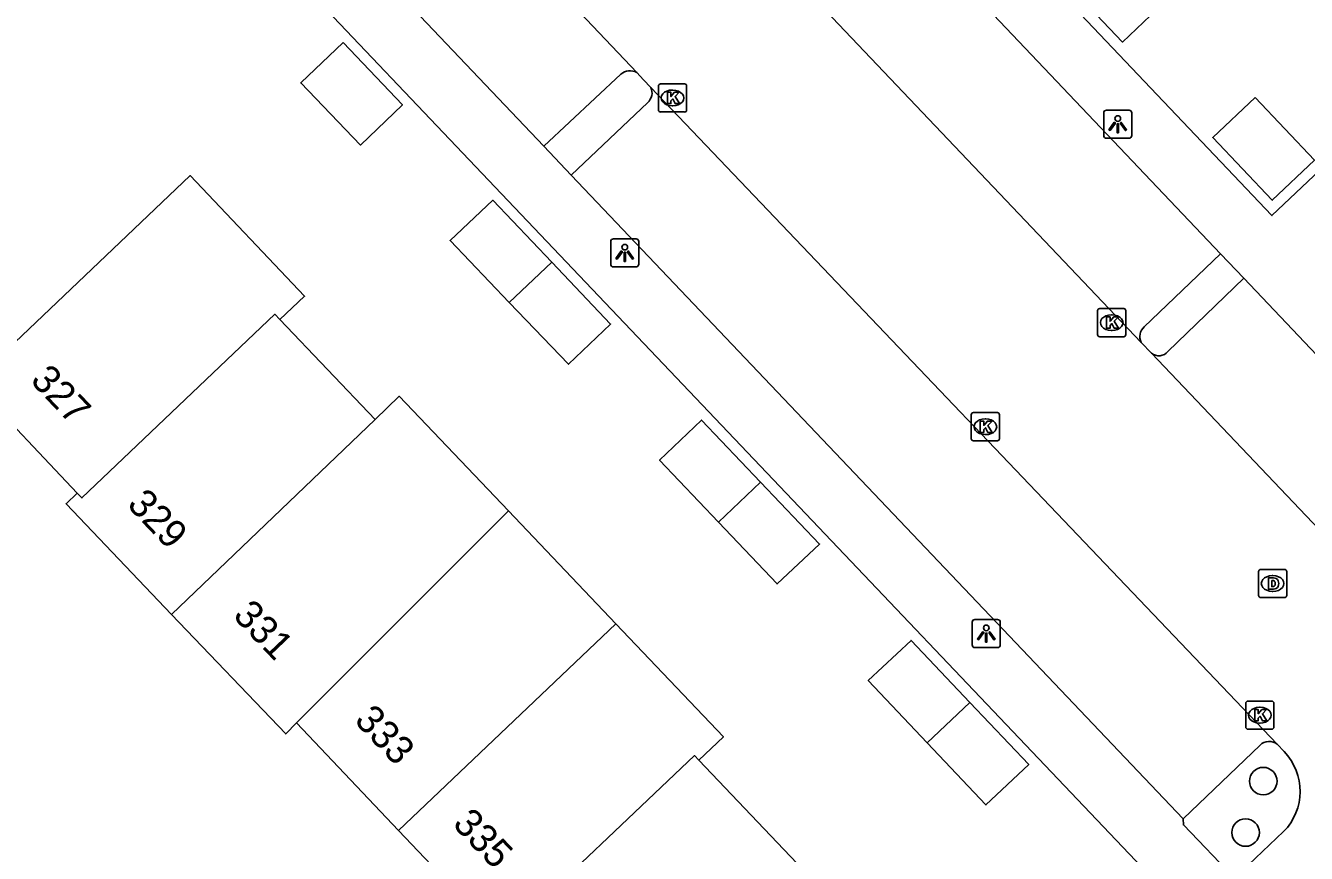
# Model space of a CAD drawing. Extents: x 162532 to 163264, y 381233 to 382042.
# Drawn here: x 163033.75 to 163079.26, y 381363.24 to 381392.66 of the extents above; entities that cross this region are included whole.
import ezdxf

# ---------------------------------------------------------------- set-up
doc = ezdxf.new("R2010")
doc.units = 0
for name, color, linetype in [('IMGEO_Boom', 7, 'Continuous'), ('IMGEO_Drainageput', 7, 'Continuous'), ('IMGEO_Kolk', 7, 'Continuous'), ('IMGEO_Lichtpunt', 7, 'Continuous'), ('IMGEO_Pand', 7, 'Continuous'), ('IMGEO_Pand_nummerreeks', 7, 'Continuous'), ('IMGEO_Parkeervlak_open', 7, 'Continuous'), ('IMGEO_Rijbaan_lokaal_open', 7, 'Continuous'), ('IMGEO_Voetpad_open', 7, 'Continuous')]:
    doc.layers.add(name, color=color, linetype=linetype)

msp = doc.modelspace()

# ---------------------------------------------------------------- linework, layer by layer
at = {"layer": 'IMGEO_Boom'}
for centre in [(163077.732, 381365.806), (163077.103, 381363.977)]:
    msp.add_circle(centre, 0.489, dxfattribs=at)
at = {"layer": 'IMGEO_Drainageput'}
for p, q in [((163077.637, 381373.33), (163078.489, 381373.33)), ((163077.562, 381372.404), (163077.562, 381373.256)), ((163078.05, 381373.11), (163078.075, 381373.11)), ((163078.563, 381373.256), (163078.563, 381372.404)), ((163078.073, 381372.55), (163078.048, 381372.55)), ((163078.489, 381372.33), (163077.637, 381372.33))]:
    msp.add_line(p, q, dxfattribs=at)
for points in [[(163077.637, 381373.33), (163078.489, 381373.33)], [(163077.562, 381372.404), (163077.562, 381373.256)], [(163077.911, 381373.03), (163077.911, 381372.63), (163078.095, 381372.63)], [(163078.095, 381373.03), (163077.911, 381373.03)], [(163078.035, 381372.94), (163078.035, 381372.721), (163078.065, 381372.721)], [(163078.066, 381372.94), (163078.035, 381372.94)], [(163078.563, 381373.256), (163078.563, 381372.404)], [(163078.489, 381372.33), (163077.637, 381372.33)]]:
    msp.add_lwpolyline(points, dxfattribs=at)
for centre, radius, start, end in [((163077.639, 381373.254), 0.0765, 91.552, 178.448), ((163077.639, 381373.254), 0.0765, 91.552, 178.448), ((163078.487, 381373.254), 0.0765, 1.552, 88.448), ((163078.487, 381373.254), 0.0765, 1.552, 88.448), ((163078.066, 381372.849), 0.0903, 22.3855, 90.2421), ((163078.097, 381372.843), 0.187, 28.2957, 90.7444), ((163077.857, 381372.827), 0.298, 349.6443, 10.9584), ((163077.963, 381372.828), 0.316, 341.5795, 19.167), ((163077.639, 381372.406), 0.0765, 181.552, 268.448), ((163077.639, 381372.406), 0.0765, 181.552, 268.448), ((163078.07, 381372.807), 0.0868, 266.5243, 336.8568), ((163078.096, 381372.822), 0.192, 269.7339, 330.7954), ((163078.487, 381372.406), 0.0765, 271.552, 358.448), ((163078.487, 381372.406), 0.0765, 271.552, 358.448)]:
    msp.add_arc(centre, radius, start, end, dxfattribs=at)
for centre, major_axis, ratio, start_param, end_param in [((163078.049, 381372.83), (-0.387, 0.002), 0.722429, 4.712389, 7.853982), ((163078.074, 381372.83), (-0.39, 0.002), 0.717154, 1.570796, 4.712389)]:
    msp.add_ellipse(centre, major_axis=major_axis, ratio=ratio, start_param=start_param, end_param=end_param, dxfattribs=at)
at = {"layer": 'IMGEO_Kolk'}
for p, q in [((163056.315, 381390.592), (163057.167, 381390.592)), ((163056.24, 381389.666), (163056.24, 381390.518)), ((163056.728, 381390.372), (163056.753, 381390.372)), ((163057.241, 381390.518), (163057.241, 381389.666)), ((163056.751, 381389.812), (163056.726, 381389.812)), ((163057.167, 381389.592), (163056.315, 381389.592)), ((163071.845, 381381.679), (163071.845, 381382.531)), ((163071.92, 381382.605), (163072.772, 381382.605)), ((163072.333, 381382.385), (163072.358, 381382.385)), ((163072.846, 381382.531), (163072.846, 381381.679)), ((163072.772, 381381.605), (163071.92, 381381.605)), ((163072.356, 381381.825), (163072.331, 381381.825)), ((163067.356, 381377.978), (163067.356, 381378.83)), ((163067.431, 381378.904), (163068.283, 381378.904)), ((163068.357, 381378.83), (163068.357, 381377.978)), ((163067.844, 381378.684), (163067.869, 381378.684)), ((163068.283, 381377.904), (163067.431, 381377.904)), ((163067.867, 381378.124), (163067.842, 381378.124)), ((163077.108, 381367.724), (163077.108, 381368.576)), ((163077.183, 381368.65), (163078.035, 381368.65)), ((163077.596, 381368.43), (163077.621, 381368.43)), ((163078.109, 381368.576), (163078.109, 381367.724)), ((163077.619, 381367.87), (163077.594, 381367.87)), ((163078.035, 381367.65), (163077.183, 381367.65))]:
    msp.add_line(p, q, dxfattribs=at)
for points in [[(163056.315, 381390.592), (163057.167, 381390.592)], [(163056.24, 381389.666), (163056.24, 381390.518)], [(163056.561, 381390.292), (163056.684, 381390.292), (163056.684, 381390.141), (163056.814, 381390.292), (163056.978, 381390.292), (163056.832, 381390.141), (163056.985, 381389.892), (163056.833, 381389.892), (163056.748, 381390.056), (163056.684, 381389.989), (163056.684, 381389.892), (163056.561, 381389.892), (163056.561, 381390.292)], [(163057.241, 381390.518), (163057.241, 381389.666)], [(163057.167, 381389.592), (163056.315, 381389.592)], [(163071.845, 381381.679), (163071.845, 381382.531)], [(163071.92, 381382.605), (163072.772, 381382.605)], [(163072.846, 381382.531), (163072.846, 381381.679)], [(163072.166, 381382.305), (163072.289, 381382.305), (163072.289, 381382.154), (163072.419, 381382.305), (163072.583, 381382.305), (163072.437, 381382.154), (163072.59, 381381.905), (163072.438, 381381.905), (163072.353, 381382.069), (163072.289, 381382.002), (163072.289, 381381.905), (163072.166, 381381.905), (163072.166, 381382.305)], [(163072.772, 381381.605), (163071.92, 381381.605)], [(163067.356, 381377.978), (163067.356, 381378.83)], [(163067.431, 381378.904), (163068.283, 381378.904)], [(163068.357, 381378.83), (163068.357, 381377.978)], [(163067.677, 381378.604), (163067.8, 381378.604), (163067.8, 381378.453), (163067.93, 381378.604), (163068.094, 381378.604), (163067.948, 381378.453), (163068.101, 381378.204), (163067.949, 381378.204), (163067.864, 381378.368), (163067.8, 381378.301), (163067.8, 381378.204), (163067.677, 381378.204), (163067.677, 381378.604)], [(163068.283, 381377.904), (163067.431, 381377.904)], [(163077.108, 381367.724), (163077.108, 381368.576)], [(163077.183, 381368.65), (163078.035, 381368.65)], [(163077.429, 381368.35), (163077.552, 381368.35), (163077.552, 381368.199), (163077.682, 381368.35), (163077.846, 381368.35), (163077.7, 381368.199), (163077.853, 381367.95), (163077.701, 381367.95), (163077.616, 381368.114), (163077.552, 381368.047), (163077.552, 381367.95), (163077.429, 381367.95), (163077.429, 381368.35)], [(163078.109, 381368.576), (163078.109, 381367.724)], [(163078.035, 381367.65), (163077.183, 381367.65)]]:
    msp.add_lwpolyline(points, dxfattribs=at)
for centre, start, end in [((163056.317, 381390.516), 91.552, 178.448), ((163056.317, 381390.516), 91.552, 178.448), ((163057.165, 381390.516), 1.552, 88.448), ((163057.165, 381390.516), 1.552, 88.448), ((163056.317, 381389.668), 181.552, 268.448), ((163056.317, 381389.668), 181.552, 268.448), ((163057.165, 381389.668), 271.552, 358.448), ((163057.165, 381389.668), 271.552, 358.448), ((163071.922, 381382.529), 91.552, 178.448), ((163071.922, 381382.529), 91.552, 178.448), ((163072.77, 381382.529), 1.552, 88.448), ((163072.77, 381382.529), 1.552, 88.448), ((163071.922, 381381.681), 181.552, 268.448), ((163071.922, 381381.681), 181.552, 268.448), ((163072.77, 381381.681), 271.552, 358.448), ((163072.77, 381381.681), 271.552, 358.448), ((163067.433, 381378.828), 91.552, 178.448), ((163067.433, 381378.828), 91.552, 178.448), ((163068.281, 381378.828), 1.552, 88.448), ((163068.281, 381378.828), 1.552, 88.448), ((163067.433, 381377.98), 181.552, 268.448), ((163067.433, 381377.98), 181.552, 268.448), ((163068.281, 381377.98), 271.552, 358.448), ((163068.281, 381377.98), 271.552, 358.448), ((163077.185, 381368.574), 91.552, 178.448), ((163077.185, 381368.574), 91.552, 178.448), ((163078.033, 381368.574), 1.552, 88.448), ((163078.033, 381368.574), 1.552, 88.448), ((163077.185, 381367.726), 181.552, 268.448), ((163077.185, 381367.726), 181.552, 268.448), ((163078.033, 381367.726), 271.552, 358.448), ((163078.033, 381367.726), 271.552, 358.448)]:
    msp.add_arc(centre, 0.0765, start, end, dxfattribs=at)
for centre, major_axis, ratio, start_param, end_param in [((163056.727, 381390.092), (-0.387, 0.002), 0.722429, 4.712389, 7.853982), ((163056.752, 381390.092), (-0.39, 0.002), 0.717154, 1.570796, 4.712389), ((163072.332, 381382.105), (-0.387, 0.002), 0.722429, 4.712389, 7.853982), ((163072.357, 381382.105), (-0.39, 0.002), 0.717154, 1.570796, 4.712389), ((163067.843, 381378.404), (-0.387, 0.002), 0.722429, 4.712389, 7.853982), ((163067.868, 381378.404), (-0.39, 0.002), 0.717154, 1.570796, 4.712389), ((163077.595, 381368.15), (-0.387, 0.002), 0.722429, 4.712389, 7.853982), ((163077.62, 381368.15), (-0.39, 0.002), 0.717154, 1.570796, 4.712389)]:
    msp.add_ellipse(centre, major_axis=major_axis, ratio=ratio, start_param=start_param, end_param=end_param, dxfattribs=at)
at = {"layer": 'IMGEO_Lichtpunt'}
for p, q in [((163072.964, 381389.656), (163072.156, 381389.656)), ((163072.964, 381389.656), (163072.156, 381389.656)), ((163072.062, 381389.561), (163072.062, 381388.754)), ((163072.062, 381389.561), (163072.062, 381388.754)), ((163073.058, 381388.754), (163073.058, 381389.561)), ((163073.058, 381388.754), (163073.058, 381389.561)), ((163072.156, 381388.66), (163072.964, 381388.66)), ((163072.156, 381388.66), (163072.964, 381388.66)), ((163054.544, 381384.988), (163054.544, 381384.181)), ((163054.544, 381384.988), (163054.544, 381384.181)), ((163055.446, 381385.083), (163054.638, 381385.083)), ((163055.446, 381385.083), (163054.638, 381385.083)), ((163055.54, 381384.181), (163055.54, 381384.988)), ((163055.54, 381384.181), (163055.54, 381384.988)), ((163054.638, 381384.087), (163055.446, 381384.087)), ((163054.638, 381384.087), (163055.446, 381384.087)), ((163067.389, 381371.455), (163067.389, 381370.648)), ((163067.389, 381371.455), (163067.389, 381370.648)), ((163068.291, 381371.55), (163067.483, 381371.55)), ((163068.291, 381371.55), (163067.483, 381371.55)), ((163068.385, 381370.648), (163068.385, 381371.455)), ((163068.385, 381370.648), (163068.385, 381371.455)), ((163067.483, 381370.554), (163068.291, 381370.554)), ((163067.483, 381370.554), (163068.291, 381370.554))]:
    msp.add_line(p, q, dxfattribs=at)
for points in [[(163072.436, 381389.225), (163072.475, 381389.197), (163072.287, 381388.935), (163072.249, 381388.962), (163072.436, 381389.225)], [(163072.648, 381389.197), (163072.686, 381389.224), (163072.873, 381388.962), (163072.834, 381388.934), (163072.648, 381389.197)], [(163072.538, 381389.177), (163072.585, 381389.177), (163072.585, 381388.855), (163072.538, 381388.855), (163072.538, 381389.177)], [(163054.918, 381384.652), (163054.957, 381384.624), (163054.769, 381384.362), (163054.731, 381384.389), (163054.918, 381384.652)], [(163055.13, 381384.624), (163055.168, 381384.651), (163055.355, 381384.389), (163055.316, 381384.361), (163055.13, 381384.624)], [(163055.02, 381384.604), (163055.067, 381384.604), (163055.067, 381384.282), (163055.02, 381384.282), (163055.02, 381384.604)], [(163067.763, 381371.119), (163067.802, 381371.091), (163067.614, 381370.829), (163067.576, 381370.856), (163067.763, 381371.119)], [(163067.865, 381371.071), (163067.912, 381371.071), (163067.912, 381370.749), (163067.865, 381370.749), (163067.865, 381371.071)], [(163067.975, 381371.091), (163068.013, 381371.118), (163068.2, 381370.856), (163068.161, 381370.828), (163067.975, 381371.091)]]:
    msp.add_lwpolyline(points, dxfattribs=at)
for centre in [(163072.561, 381389.359), (163055.043, 381384.786), (163067.888, 381371.253)]:
    msp.add_circle(centre, 0.0994, dxfattribs=at)
for centre, start, end in [((163072.156, 381389.561), 90, 180), ((163072.156, 381389.561), 90, 180), ((163072.964, 381389.561), 0, 90), ((163072.964, 381389.561), 0, 90), ((163072.156, 381388.754), 180, 270), ((163072.156, 381388.754), 180, 270), ((163072.964, 381388.754), 270, 0), ((163072.964, 381388.754), 270, 360), ((163054.638, 381384.988), 90, 180), ((163054.638, 381384.988), 90, 180), ((163055.446, 381384.988), 0, 90), ((163055.446, 381384.988), 0, 90), ((163054.638, 381384.181), 180, 270), ((163054.638, 381384.181), 180, 270), ((163055.446, 381384.181), 270, 0), ((163055.446, 381384.181), 270, 360), ((163067.483, 381371.455), 90, 180), ((163067.483, 381371.455), 90, 180), ((163068.291, 381371.455), 0, 90), ((163068.291, 381371.455), 0, 90), ((163067.483, 381370.648), 180, 270), ((163067.483, 381370.648), 180, 270), ((163068.291, 381370.648), 270, 0), ((163068.291, 381370.648), 270, 360)]:
    msp.add_arc(centre, 0.0946, start, end, dxfattribs=at)
at = {"layer": 'IMGEO_Pand'}
for points in [[(163072.138, 381395.704), (163074.225, 381393.502), (163072.725, 381392.079), (163070.639, 381394.282)], [(163045.031, 381392.064), (163047.14, 381389.843), (163045.649, 381388.418), (163043.527, 381390.626), (163045.031, 381392.064)], [(163077.448, 381390.103), (163079.557, 381387.878), (163078.051, 381386.454), (163075.938, 381388.685), (163077.448, 381390.103)], [(163042.79, 381382.214), (163043.664, 381383.044), (163039.595, 381387.329), (163031.866, 381379.972), (163035.586, 381376.048)], [(163052.448, 381384.253), (163050.357, 381386.455), (163048.836, 381385.02), (163050.939, 381382.82)], [(163050.939, 381382.82), (163052.448, 381384.253)], [(163050.939, 381382.82), (163053.039, 381380.623), (163054.539, 381382.05), (163052.448, 381384.253)], [(163035.586, 381376.048), (163035.752, 381375.873), (163042.612, 381382.401), (163042.79, 381382.214)], [(163046.168, 381378.664), (163042.79, 381382.214)], [(163046.168, 381378.664), (163047.029, 381379.49), (163050.906, 381375.416)], [(163038.942, 381371.732), (163046.168, 381378.664)], [(163059.87, 381376.436), (163057.775, 381378.642), (163056.28, 381377.215), (163058.37, 381375.012)], [(163035.586, 381376.048), (163035.188, 381375.668), (163038.942, 381371.732)], [(163058.37, 381375.012), (163059.87, 381376.436)], [(163058.37, 381375.012), (163060.453, 381372.817), (163061.965, 381374.23), (163059.87, 381376.436)], [(163043.383, 381367.874), (163050.906, 381375.416)], [(163050.906, 381375.416), (163054.728, 381371.4)], [(163043.383, 381367.874), (163042.994, 381367.484), (163038.942, 381371.732)], [(163054.728, 381371.4), (163047.008, 381364.053)], [(163057.673, 381366.549), (163058.55, 381367.383), (163054.728, 381371.4)], [(163067.307, 381368.603), (163065.214, 381370.807), (163063.696, 381369.379), (163065.793, 381367.165)], [(163065.793, 381367.165), (163067.307, 381368.603)], [(163065.793, 381367.165), (163067.878, 381364.963), (163069.4, 381366.399), (163067.307, 381368.603)], [(163047.008, 381364.053), (163043.383, 381367.874)], [(163050.507, 381360.366), (163050.667, 381360.198), (163057.516, 381366.714), (163057.673, 381366.549)], [(163061.396, 381362.636), (163057.673, 381366.549)], [(163047.008, 381364.053), (163050.507, 381360.366)]]:
    msp.add_lwpolyline(points, dxfattribs=at)
at = {"layer": 'IMGEO_Parkeervlak_open'}
for points in [[(163054.907, 381390.941), (163052.172, 381388.376)], [(163053.143, 381387.343), (163055.86, 381389.927)], [(163076.209, 381384.545), (163073.503, 381381.951)], [(163074.34, 381381.081), (163077.037, 381383.681)], [(163077.618, 381367.083), (163074.889, 381364.471)]]:
    msp.add_lwpolyline(points, dxfattribs=at)
for centre, radius, start, end in [((163055.224, 381390.574), 0.485, 60.0528, 130.7795), ((163055.545, 381390.273), 0.467, 312.3291, 23.7747), ((163073.791, 381381.609), 0.447, 130.1451, 207.5965), ((163074.019, 381381.338), 0.412, 231.2544, 321.3608), ((163077.942, 381366.756), 0.461, 51.8166, 134.7618)]:
    msp.add_arc(centre, radius, start, end, dxfattribs=at)
at = {"layer": 'IMGEO_Rijbaan_lokaal_open'}
for points in [[(163073.395, 381381.402), (163047.55, 381408.608)], [(163042.921, 381404.231), (163055.466, 381390.994)], [(163055.973, 381390.461), (163055.712, 381390.735), (163055.466, 381390.994)], [(163078.227, 381367.118), (163055.973, 381390.461)], [(163073.395, 381381.402), (163073.761, 381381.017)], [(163073.761, 381381.017), (163086.348, 381367.767)], [(163078.474, 381366.857), (163078.227, 381367.118)], [(163076.711, 381362.355), (163078.452, 381364.011)]]:
    msp.add_lwpolyline(points, dxfattribs=at)
msp.add_arc((163077, 381365.445), 2.041, 315.3438, 43.7704, dxfattribs=at)
at = {"layer": 'IMGEO_Voetpad_open'}
for points in [[(163058.801, 381420.628), (163058.749, 381420.683), (163051.544, 381413.821), (163078.037, 381385.91), (163085.304, 381392.789), (163085.216, 381392.882)], [(163076.209, 381384.545), (163050.886, 381411.231)], [(163035.996, 381401.387), (163036.717, 381400.603), (163037.105, 381400.96), (163075.261, 381360.801), (163068.927, 381354.721), (163068.843, 381354.809)], [(163040.159, 381401.017), (163052.172, 381388.376)], [(163052.172, 381388.376), (163053.143, 381387.343)], [(163053.143, 381387.343), (163074.889, 381364.471)], [(163077.037, 381383.681), (163076.209, 381384.545)], [(163089.13, 381370.926), (163077.037, 381383.681)], [(163074.889, 381364.471), (163074.894, 381364.25), (163076.711, 381362.355)]]:
    msp.add_lwpolyline(points, dxfattribs=at)

# ---------------------------------------------------------------- texts
at = {"layer": 'IMGEO_Pand_nummerreeks'}
for s, rotation, p in [('327', 313.4701, (163033.887, 381380.021)), ('329', 313.6477, (163037.322, 381375.605)), ('331', 313.6477, (163041.087, 381371.657)), ('333', 313.4987, (163045.397, 381367.931)), ('335', 313.4987, (163048.89, 381364.25))]:
    msp.add_text(s, height=1, rotation=rotation, dxfattribs=at).set_placement(p)

doc.saveas('drawing.dxf')
